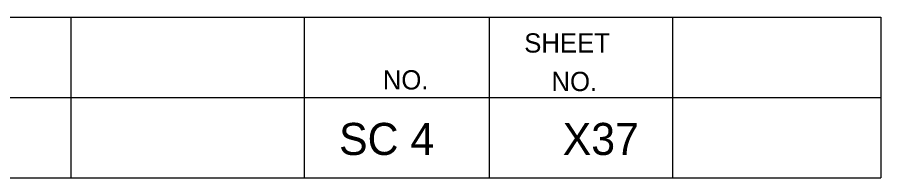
# Model space of a CAD drawing. Extents: x 1000 to 1162, y 999 to 8520.
# Drawn here: x 1148.08 to 1161.56, y 5240.05 to 5242.55 of the extents above; entities that cross this region are included whole.
import ezdxf

# ---------------------------------------------------------------- set-up
doc = ezdxf.new("R2010")
doc.units = 0
doc.layers.add('Level 20', color=7, linetype='Continuous')
doc.layers.add('Level 3', color=7, linetype='Continuous')

msp = doc.modelspace()

# ---------------------------------------------------------------- linework, layer by layer
at = {"layer": 'Level 3'}
for p, q in [((1133.055, 5242.546), (1161.555, 5242.546)), ((1133.055, 5242.546), (1161.555, 5242.546)), ((1133.055, 5242.546), (1161.555, 5242.546)), ((1133.055, 5242.546), (1161.555, 5242.546)), ((1133.055, 5242.546), (1161.555, 5242.546)), ((1133.055, 5242.546), (1161.555, 5242.546)), ((1133.055, 5242.546), (1161.555, 5242.546)), ((1133.055, 5242.546), (1161.555, 5242.546)), ((1133.055, 5242.546), (1161.555, 5242.546)), ((1133.055, 5242.546), (1161.555, 5242.546)), ((1133.055, 5242.546), (1161.555, 5242.546)), ((1133.055, 5242.546), (1161.555, 5242.546)), ((1133.055, 5242.546), (1161.555, 5242.546)), ((1133.055, 5242.546), (1161.555, 5242.546)), ((1133.055, 5242.546), (1161.555, 5242.546)), ((1133.055, 5242.546), (1161.555, 5242.546)), ((1133.055, 5242.546), (1161.555, 5242.546)), ((1133.055, 5242.546), (1161.555, 5242.546)), ((1133.055, 5242.546), (1161.555, 5242.546)), ((1133.055, 5242.546), (1161.555, 5242.546)), ((1133.055, 5242.546), (1161.555, 5242.546)), ((1133.055, 5242.546), (1161.555, 5242.546)), ((1133.055, 5242.546), (1161.555, 5242.546)), ((1133.055, 5242.546), (1161.555, 5242.546)), ((1133.055, 5242.546), (1161.555, 5242.546)), ((1133.055, 5242.546), (1161.555, 5242.546)), ((1133.055, 5242.546), (1161.555, 5242.546)), ((1133.055, 5242.546), (1161.555, 5242.546)), ((1133.055, 5242.546), (1161.555, 5242.546)), ((1133.055, 5242.546), (1161.555, 5242.546)), ((1133.055, 5242.546), (1161.555, 5242.546)), ((1133.055, 5242.546), (1161.555, 5242.546)), ((1133.055, 5242.546), (1161.555, 5242.546)), ((1133.055, 5242.546), (1161.555, 5242.546)), ((1133.055, 5242.546), (1161.555, 5242.546)), ((1148.913, 5242.546), (1148.913, 5240.046)), ((1148.913, 5242.546), (1148.913, 5240.046)), ((1148.913, 5242.546), (1148.913, 5240.046)), ((1148.913, 5242.546), (1148.913, 5240.046)), ((1148.913, 5242.546), (1148.913, 5240.046)), ((1148.913, 5242.546), (1148.913, 5240.046)), ((1148.913, 5242.546), (1148.913, 5240.046)), ((1148.913, 5242.546), (1148.913, 5240.046)), ((1148.913, 5242.546), (1148.913, 5240.046)), ((1148.913, 5242.546), (1148.913, 5240.046)), ((1148.913, 5242.546), (1148.913, 5240.046)), ((1148.913, 5242.546), (1148.913, 5240.046)), ((1148.913, 5242.546), (1148.913, 5240.046)), ((1148.913, 5242.546), (1148.913, 5240.046)), ((1148.913, 5242.546), (1148.913, 5240.046)), ((1148.913, 5242.546), (1148.913, 5240.046)), ((1148.913, 5242.546), (1148.913, 5240.046)), ((1148.913, 5242.546), (1148.913, 5240.046)), ((1148.913, 5242.546), (1148.913, 5240.046)), ((1148.913, 5242.546), (1148.913, 5240.046)), ((1148.913, 5242.546), (1148.913, 5240.046)), ((1148.913, 5242.546), (1148.913, 5240.046)), ((1148.913, 5242.546), (1148.913, 5240.046)), ((1148.913, 5242.546), (1148.913, 5240.046)), ((1148.913, 5242.546), (1148.913, 5240.046)), ((1148.913, 5242.546), (1148.913, 5240.046)), ((1148.913, 5242.546), (1148.913, 5240.046)), ((1148.913, 5242.546), (1148.913, 5240.046)), ((1148.913, 5242.546), (1148.913, 5240.046)), ((1148.913, 5242.546), (1148.913, 5240.046)), ((1148.913, 5242.546), (1148.913, 5240.046)), ((1148.913, 5242.546), (1148.913, 5240.046)), ((1148.913, 5242.546), (1148.913, 5240.046)), ((1148.913, 5242.546), (1148.913, 5240.046)), ((1148.913, 5242.546), (1148.913, 5240.046)), ((1152.554, 5242.546), (1152.554, 5240.046)), ((1152.554, 5242.546), (1152.554, 5240.046)), ((1152.554, 5242.546), (1152.554, 5240.046)), ((1152.554, 5242.546), (1152.554, 5240.046)), ((1152.554, 5242.546), (1152.554, 5240.046)), ((1152.554, 5242.546), (1152.554, 5240.046)), ((1152.554, 5242.546), (1152.554, 5240.046)), ((1152.554, 5242.546), (1152.554, 5240.046)), ((1152.554, 5242.546), (1152.554, 5240.046)), ((1152.554, 5242.546), (1152.554, 5240.046)), ((1152.554, 5242.546), (1152.554, 5240.046)), ((1152.554, 5242.546), (1152.554, 5240.046)), ((1152.554, 5242.546), (1152.554, 5240.046)), ((1152.554, 5242.546), (1152.554, 5240.046)), ((1152.554, 5242.546), (1152.554, 5240.046)), ((1152.554, 5242.546), (1152.554, 5240.046)), ((1152.554, 5242.546), (1152.554, 5240.046)), ((1152.554, 5242.546), (1152.554, 5240.046)), ((1152.554, 5242.546), (1152.554, 5240.046)), ((1152.554, 5242.546), (1152.554, 5240.046)), ((1152.554, 5242.546), (1152.554, 5240.046)), ((1152.554, 5242.546), (1152.554, 5240.046)), ((1152.554, 5242.546), (1152.554, 5240.046)), ((1152.554, 5242.546), (1152.554, 5240.046)), ((1152.554, 5242.546), (1152.554, 5240.046)), ((1152.554, 5242.546), (1152.554, 5240.046)), ((1152.554, 5242.546), (1152.554, 5240.046)), ((1152.554, 5242.546), (1152.554, 5240.046)), ((1152.554, 5242.546), (1152.554, 5240.046)), ((1152.554, 5242.546), (1152.554, 5240.046)), ((1152.554, 5242.546), (1152.554, 5240.046)), ((1152.554, 5242.546), (1152.554, 5240.046)), ((1152.554, 5242.546), (1152.554, 5240.046)), ((1152.554, 5242.546), (1152.554, 5240.046)), ((1152.554, 5242.546), (1152.554, 5240.046)), ((1155.44, 5242.546), (1155.44, 5240.046)), ((1155.44, 5242.546), (1155.44, 5240.046)), ((1155.44, 5242.546), (1155.44, 5240.046)), ((1155.44, 5242.546), (1155.44, 5240.046)), ((1155.44, 5242.546), (1155.44, 5240.046)), ((1155.44, 5242.546), (1155.44, 5240.046)), ((1155.44, 5242.546), (1155.44, 5240.046)), ((1155.44, 5242.546), (1155.44, 5240.046)), ((1155.44, 5242.546), (1155.44, 5240.046)), ((1155.44, 5242.546), (1155.44, 5240.046)), ((1155.44, 5242.546), (1155.44, 5240.046)), ((1155.44, 5242.546), (1155.44, 5240.046)), ((1155.44, 5242.546), (1155.44, 5240.046)), ((1155.44, 5242.546), (1155.44, 5240.046)), ((1155.44, 5242.546), (1155.44, 5240.046)), ((1155.44, 5242.546), (1155.44, 5240.046)), ((1155.44, 5242.546), (1155.44, 5240.046)), ((1155.44, 5242.546), (1155.44, 5240.046)), ((1155.44, 5242.546), (1155.44, 5240.046)), ((1155.44, 5242.546), (1155.44, 5240.046)), ((1155.44, 5242.546), (1155.44, 5240.046)), ((1155.44, 5242.546), (1155.44, 5240.046)), ((1155.44, 5242.546), (1155.44, 5240.046)), ((1155.44, 5242.546), (1155.44, 5240.046)), ((1155.44, 5242.546), (1155.44, 5240.046)), ((1155.44, 5242.546), (1155.44, 5240.046)), ((1155.44, 5242.546), (1155.44, 5240.046)), ((1155.44, 5242.546), (1155.44, 5240.046)), ((1155.44, 5242.546), (1155.44, 5240.046)), ((1155.44, 5242.546), (1155.44, 5240.046)), ((1155.44, 5242.546), (1155.44, 5240.046)), ((1155.44, 5242.546), (1155.44, 5240.046)), ((1155.44, 5242.546), (1155.44, 5240.046)), ((1155.44, 5242.546), (1155.44, 5240.046)), ((1155.44, 5242.546), (1155.44, 5240.046)), ((1158.305, 5242.546), (1158.305, 5240.046)), ((1158.305, 5242.546), (1158.305, 5240.046)), ((1158.305, 5242.546), (1158.305, 5240.046)), ((1158.305, 5242.546), (1158.305, 5240.046)), ((1158.305, 5242.546), (1158.305, 5240.046)), ((1158.305, 5242.546), (1158.305, 5240.046)), ((1158.305, 5242.546), (1158.305, 5240.046)), ((1158.305, 5242.546), (1158.305, 5240.046)), ((1158.305, 5242.546), (1158.305, 5240.046)), ((1158.305, 5242.546), (1158.305, 5240.046)), ((1158.305, 5242.546), (1158.305, 5240.046)), ((1158.305, 5242.546), (1158.305, 5240.046)), ((1158.305, 5242.546), (1158.305, 5240.046)), ((1158.305, 5242.546), (1158.305, 5240.046)), ((1158.305, 5242.546), (1158.305, 5240.046)), ((1158.305, 5242.546), (1158.305, 5240.046)), ((1158.305, 5242.546), (1158.305, 5240.046)), ((1158.305, 5242.546), (1158.305, 5240.046)), ((1158.305, 5242.546), (1158.305, 5240.046)), ((1158.305, 5242.546), (1158.305, 5240.046)), ((1158.305, 5242.546), (1158.305, 5240.046)), ((1158.305, 5242.546), (1158.305, 5240.046)), ((1158.305, 5242.546), (1158.305, 5240.046)), ((1158.305, 5242.546), (1158.305, 5240.046)), ((1158.305, 5242.546), (1158.305, 5240.046)), ((1158.305, 5242.546), (1158.305, 5240.046)), ((1158.305, 5242.546), (1158.305, 5240.046)), ((1158.305, 5242.546), (1158.305, 5240.046)), ((1158.305, 5242.546), (1158.305, 5240.046)), ((1158.305, 5242.546), (1158.305, 5240.046)), ((1158.305, 5242.546), (1158.305, 5240.046)), ((1158.305, 5242.546), (1158.305, 5240.046)), ((1158.305, 5242.546), (1158.305, 5240.046)), ((1158.305, 5242.546), (1158.305, 5240.046)), ((1158.305, 5242.546), (1158.305, 5240.046)), ((1161.555, 5242.546), (1161.555, 5240.046)), ((1161.555, 5242.546), (1161.555, 5240.046)), ((1161.555, 5242.546), (1161.555, 5240.046)), ((1161.555, 5242.546), (1161.555, 5240.046)), ((1161.555, 5242.546), (1161.555, 5240.046)), ((1161.555, 5242.546), (1161.555, 5240.046)), ((1161.555, 5242.546), (1161.555, 5240.046)), ((1161.555, 5242.546), (1161.555, 5240.046)), ((1161.555, 5242.546), (1161.555, 5240.046)), ((1161.555, 5242.546), (1161.555, 5240.046)), ((1161.555, 5242.546), (1161.555, 5240.046)), ((1161.555, 5242.546), (1161.555, 5240.046)), ((1161.555, 5242.546), (1161.555, 5240.046)), ((1161.555, 5242.546), (1161.555, 5240.046)), ((1161.555, 5242.546), (1161.555, 5240.046)), ((1161.555, 5242.546), (1161.555, 5240.046)), ((1161.555, 5242.546), (1161.555, 5240.046)), ((1161.555, 5242.546), (1161.555, 5240.046)), ((1161.555, 5242.546), (1161.555, 5240.046)), ((1161.555, 5242.546), (1161.555, 5240.046)), ((1161.555, 5242.546), (1161.555, 5240.046)), ((1161.555, 5242.546), (1161.555, 5240.046)), ((1161.555, 5242.546), (1161.555, 5240.046)), ((1161.555, 5242.546), (1161.555, 5240.046)), ((1161.555, 5242.546), (1161.555, 5240.046)), ((1161.555, 5242.546), (1161.555, 5240.046)), ((1161.555, 5242.546), (1161.555, 5240.046)), ((1161.555, 5242.546), (1161.555, 5240.046)), ((1161.555, 5242.546), (1161.555, 5240.046)), ((1161.555, 5242.546), (1161.555, 5240.046)), ((1161.555, 5242.546), (1161.555, 5240.046)), ((1161.555, 5242.546), (1161.555, 5240.046)), ((1161.555, 5242.546), (1161.555, 5240.046)), ((1161.555, 5242.546), (1161.555, 5240.046)), ((1161.555, 5242.546), (1161.555, 5240.046)), ((1133.055, 5241.296), (1161.555, 5241.296)), ((1133.055, 5241.296), (1161.555, 5241.296)), ((1133.055, 5241.296), (1161.555, 5241.296)), ((1133.055, 5241.296), (1161.555, 5241.296)), ((1133.055, 5241.296), (1161.555, 5241.296)), ((1133.055, 5241.296), (1161.555, 5241.296)), ((1133.055, 5241.296), (1161.555, 5241.296)), ((1133.055, 5241.296), (1161.555, 5241.296)), ((1133.055, 5241.296), (1161.555, 5241.296)), ((1133.055, 5241.296), (1161.555, 5241.296)), ((1133.055, 5241.296), (1161.555, 5241.296)), ((1133.055, 5241.296), (1161.555, 5241.296)), ((1133.055, 5241.296), (1161.555, 5241.296)), ((1133.055, 5241.296), (1161.555, 5241.296)), ((1133.055, 5241.296), (1161.555, 5241.296)), ((1133.055, 5241.296), (1161.555, 5241.296)), ((1133.055, 5241.296), (1161.555, 5241.296)), ((1133.055, 5241.296), (1161.555, 5241.296)), ((1133.055, 5241.296), (1161.555, 5241.296)), ((1133.055, 5241.296), (1161.555, 5241.296)), ((1133.055, 5241.296), (1161.555, 5241.296)), ((1133.055, 5241.296), (1161.555, 5241.296)), ((1133.055, 5241.296), (1161.555, 5241.296)), ((1133.055, 5241.296), (1161.555, 5241.296)), ((1133.055, 5241.296), (1161.555, 5241.296)), ((1133.055, 5241.296), (1161.555, 5241.296)), ((1133.055, 5241.296), (1161.555, 5241.296)), ((1133.055, 5241.296), (1161.555, 5241.296)), ((1133.055, 5241.296), (1161.555, 5241.296)), ((1133.055, 5241.296), (1161.555, 5241.296)), ((1133.055, 5241.296), (1161.555, 5241.296)), ((1133.055, 5241.296), (1161.555, 5241.296)), ((1133.055, 5241.296), (1161.555, 5241.296)), ((1133.055, 5241.296), (1161.555, 5241.296)), ((1133.055, 5241.296), (1161.555, 5241.296)), ((1133.055, 5240.046), (1161.555, 5240.046)), ((1133.055, 5240.046), (1161.555, 5240.046)), ((1133.055, 5240.046), (1161.555, 5240.046)), ((1133.055, 5240.046), (1161.555, 5240.046)), ((1133.055, 5240.046), (1161.555, 5240.046)), ((1133.055, 5240.046), (1161.555, 5240.046)), ((1133.055, 5240.046), (1161.555, 5240.046)), ((1133.055, 5240.046), (1161.555, 5240.046)), ((1133.055, 5240.046), (1161.555, 5240.046)), ((1133.055, 5240.046), (1161.555, 5240.046)), ((1133.055, 5240.046), (1161.555, 5240.046)), ((1133.055, 5240.046), (1161.555, 5240.046)), ((1133.055, 5240.046), (1161.555, 5240.046)), ((1133.055, 5240.046), (1161.555, 5240.046)), ((1133.055, 5240.046), (1161.555, 5240.046)), ((1133.055, 5240.046), (1161.555, 5240.046)), ((1133.055, 5240.046), (1161.555, 5240.046)), ((1133.055, 5240.046), (1161.555, 5240.046)), ((1133.055, 5240.046), (1161.555, 5240.046)), ((1133.055, 5240.046), (1161.555, 5240.046)), ((1133.055, 5240.046), (1161.555, 5240.046)), ((1133.055, 5240.046), (1161.555, 5240.046)), ((1133.055, 5240.046), (1161.555, 5240.046)), ((1133.055, 5240.046), (1161.555, 5240.046)), ((1133.055, 5240.046), (1161.555, 5240.046)), ((1133.055, 5240.046), (1161.555, 5240.046)), ((1133.055, 5240.046), (1161.555, 5240.046)), ((1133.055, 5240.046), (1161.555, 5240.046)), ((1133.055, 5240.046), (1161.555, 5240.046)), ((1133.055, 5240.046), (1161.555, 5240.046)), ((1133.055, 5240.046), (1161.555, 5240.046)), ((1133.055, 5240.046), (1161.555, 5240.046)), ((1133.055, 5240.046), (1161.555, 5240.046)), ((1133.055, 5240.046), (1161.555, 5240.046)), ((1133.055, 5240.046), (1161.555, 5240.046))]:
    msp.add_line(p, q, dxfattribs=at)

# ---------------------------------------------------------------- texts
at = {"layer": 'Level 20'}
for s, p in [('SC 4', (1153.099, 5240.4)), ('X37', (1156.59, 5240.4))]:
    msp.add_text(s, height=0.5, dxfattribs=at).set_placement(p)
at = {"layer": 'Level 3'}
for s, p in [('SHEET', (1155.99, 5241.996)), ('SHEET', (1155.99, 5241.996)), ('SHEET', (1155.99, 5241.996)), ('SHEET', (1155.99, 5241.996)), ('SHEET', (1155.99, 5241.996)), ('SHEET', (1155.99, 5241.996)), ('SHEET', (1155.99, 5241.996)), ('SHEET', (1155.99, 5241.996)), ('SHEET', (1155.99, 5241.996)), ('SHEET', (1155.99, 5241.996)), ('SHEET', (1155.99, 5241.996)), ('SHEET', (1155.99, 5241.996)), ('SHEET', (1155.99, 5241.996)), ('SHEET', (1155.99, 5241.996)), ('SHEET', (1155.99, 5241.996)), ('SHEET', (1155.99, 5241.996)), ('SHEET', (1155.99, 5241.996)), ('SHEET', (1155.99, 5241.996)), ('SHEET', (1155.99, 5241.996)), ('SHEET', (1155.99, 5241.996)), ('SHEET', (1155.99, 5241.996)), ('SHEET', (1155.99, 5241.996)), ('SHEET', (1155.99, 5241.996)), ('SHEET', (1155.99, 5241.996)), ('SHEET', (1155.99, 5241.996)), ('SHEET', (1155.99, 5241.996)), ('SHEET', (1155.99, 5241.996)), ('SHEET', (1155.99, 5241.996)), ('SHEET', (1155.99, 5241.996)), ('SHEET', (1155.99, 5241.996)), ('SHEET', (1155.99, 5241.996)), ('SHEET', (1155.99, 5241.996)), ('SHEET', (1155.99, 5241.996)), ('SHEET', (1155.99, 5241.996)), ('SHEET', (1155.99, 5241.996)), ('NO.', (1153.782, 5241.421)), ('NO.', (1153.782, 5241.421)), ('NO.', (1153.782, 5241.421)), ('NO.', (1153.782, 5241.421)), ('NO.', (1153.782, 5241.421)), ('NO.', (1153.782, 5241.421)), ('NO.', (1153.782, 5241.421)), ('NO.', (1153.782, 5241.421)), ('NO.', (1153.782, 5241.421)), ('NO.', (1153.782, 5241.421)), ('NO.', (1153.782, 5241.421)), ('NO.', (1153.782, 5241.421)), ('NO.', (1153.782, 5241.421)), ('NO.', (1153.782, 5241.421)), ('NO.', (1153.782, 5241.421)), ('NO.', (1153.782, 5241.421)), ('NO.', (1153.782, 5241.421)), ('NO.', (1153.782, 5241.421)), ('NO.', (1153.782, 5241.421)), ('NO.', (1153.782, 5241.421)), ('NO.', (1153.782, 5241.421)), ('NO.', (1153.782, 5241.421)), ('NO.', (1153.782, 5241.421)), ('NO.', (1153.782, 5241.421)), ('NO.', (1153.782, 5241.421)), ('NO.', (1153.782, 5241.421)), ('NO.', (1153.782, 5241.421)), ('NO.', (1153.782, 5241.421)), ('NO.', (1153.782, 5241.421)), ('NO.', (1153.782, 5241.421)), ('NO.', (1153.782, 5241.421)), ('NO.', (1153.782, 5241.421)), ('NO.', (1153.782, 5241.421)), ('NO.', (1153.782, 5241.421)), ('NO.', (1153.782, 5241.421)), ('NO.', (1156.415, 5241.396)), ('NO.', (1156.415, 5241.396)), ('NO.', (1156.415, 5241.396)), ('NO.', (1156.415, 5241.396)), ('NO.', (1156.415, 5241.396)), ('NO.', (1156.415, 5241.396)), ('NO.', (1156.415, 5241.396)), ('NO.', (1156.415, 5241.396)), ('NO.', (1156.415, 5241.396)), ('NO.', (1156.415, 5241.396)), ('NO.', (1156.415, 5241.396)), ('NO.', (1156.415, 5241.396)), ('NO.', (1156.415, 5241.396)), ('NO.', (1156.415, 5241.396)), ('NO.', (1156.415, 5241.396)), ('NO.', (1156.415, 5241.396)), ('NO.', (1156.415, 5241.396)), ('NO.', (1156.415, 5241.396)), ('NO.', (1156.415, 5241.396)), ('NO.', (1156.415, 5241.396)), ('NO.', (1156.415, 5241.396)), ('NO.', (1156.415, 5241.396)), ('NO.', (1156.415, 5241.396)), ('NO.', (1156.415, 5241.396)), ('NO.', (1156.415, 5241.396)), ('NO.', (1156.415, 5241.396)), ('NO.', (1156.415, 5241.396)), ('NO.', (1156.415, 5241.396)), ('NO.', (1156.415, 5241.396)), ('NO.', (1156.415, 5241.396)), ('NO.', (1156.415, 5241.396)), ('NO.', (1156.415, 5241.396)), ('NO.', (1156.415, 5241.396)), ('NO.', (1156.415, 5241.396)), ('NO.', (1156.415, 5241.396))]:
    msp.add_text(s, height=0.3, dxfattribs=at).set_placement(p)

doc.saveas('drawing.dxf')
